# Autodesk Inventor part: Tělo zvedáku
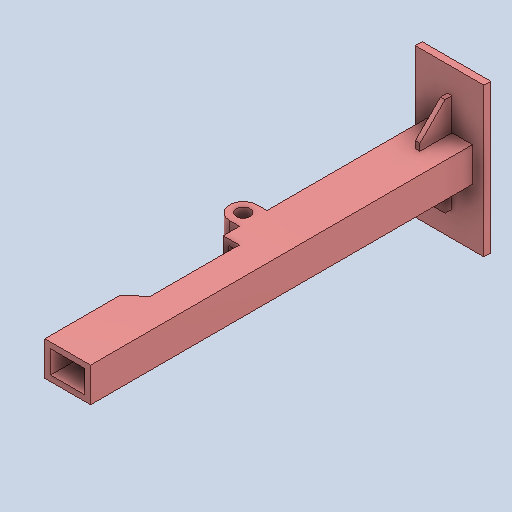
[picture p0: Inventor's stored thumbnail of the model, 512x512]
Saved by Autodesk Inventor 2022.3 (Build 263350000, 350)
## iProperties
Created: 2022-03
Part Number: Tělo zvedáku
Material: Všeobecné
Document SubType Name: Modeling
Designer: Hra42
Density: 1 g/cm^3
Appearance: Výchozí
Author: Hra42
Sending System: SolidWorks 2012
Last Author: Hra42
Last Saved: 2025-11-13
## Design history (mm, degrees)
feature "Importovaný1"
node "Těleso1"
